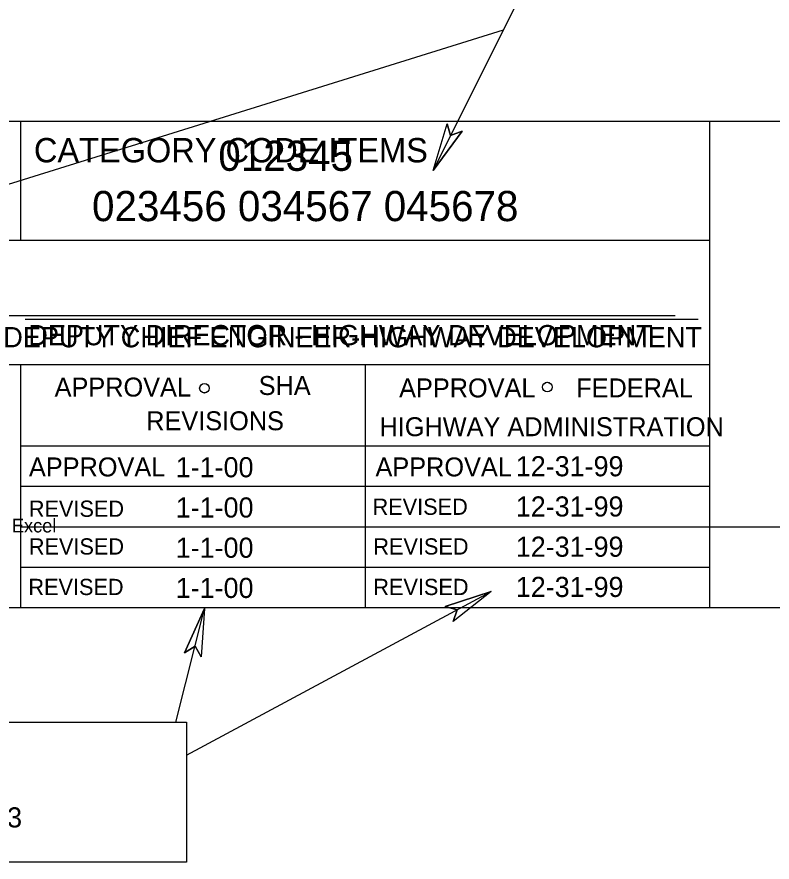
# Model space of a CAD drawing. Extents: x -0.5 to 21.6, y 4.3 to 17.8.
# Drawn here: x 1.229 to 3.481, y 5.179 to 7.7 of the extents above; entities that cross this region are included whole.
import ezdxf

# ---------------------------------------------------------------- set-up
doc = ezdxf.new("R2010")
doc.units = 0
for name, color, linetype in [('DETL-DIMS', 7, 'Continuous'), ('DETL-LINE', 7, 'Continuous'), ('DETL-NOTE', 7, 'Continuous'), ('TTLB-TEXT', 7, 'Continuous'), ('USER-BORD', 7, 'Continuous')]:
    doc.layers.add(name, color=color, linetype=linetype)

msp = doc.modelspace()

# ---------------------------------------------------------------- linework, layer by layer
at = {"layer": 'DETL-DIMS'}
for p, q in [((2.7192, 7.74), (2.4706, 7.2422)), ((2.6792, 7.6599), (1.0734, 7.16)), ((2.4706, 7.2422), (2.512, 7.3814)), ((2.5224, 7.346), (2.512, 7.3814)), ((2.4706, 7.2422), (2.557, 7.3589)), ((2.557, 7.3589), (2.5224, 7.346)), ((1.7345, 5.4977), (2.6438, 5.9866)), ((2.6438, 5.9866), (2.5059, 5.9411)), ((2.6438, 5.9866), (2.5298, 5.8967)), ((1.7034, 5.5961), (1.7884, 5.9359)), ((1.7884, 5.9359), (1.7293, 5.8033)), ((1.7884, 5.9359), (1.7782, 5.7911)), ((2.5059, 5.9411), (2.5416, 5.9317)), ((2.5416, 5.9317), (2.5298, 5.8967)), ((1.7293, 5.8033), (1.7603, 5.8234)), ((1.7603, 5.8234), (1.7782, 5.7911))]:
    msp.add_line(p, q, dxfattribs=at)
for points in [[(2.557, 7.3589), (2.4706, 7.2422), (2.512, 7.3814), (2.5224, 7.346)], [(2.5059, 5.9411), (2.6438, 5.9866), (2.5298, 5.8967), (2.5416, 5.9317)], [(1.7293, 5.8033), (1.7884, 5.9359), (1.7782, 5.7911), (1.7603, 5.8234)]]:
    msp.add_lwpolyline(points, close=True, dxfattribs=at)
at = {"layer": 'DETL-LINE'}
msp.add_lwpolyline([(0.3943, 14.1527), (0.3943, 16.2906), (7.7685, 16.2906), (7.7685, 5.9375), (0.3943, 5.9375), (0.3943, 13.6862)], dxfattribs=at)
at = {"layer": 'DETL-NOTE'}
for p, q in [((1.1851, 6.8093), (3.192, 6.8093)), ((1.2535, 6.7985), (3.2604, 6.7985))]:
    msp.add_line(p, q, dxfattribs=at)
for centre in [(1.7884, 6.5926), (2.811, 6.5959)]:
    msp.add_ellipse(centre, major_axis=(0, -0.0143), ratio=0.999903, dxfattribs=at)
at = {"layer": 'TTLB-TEXT'}
for p, q in [((7.7685, 7.3883), (0.3943, 7.3883)), ((1.2405, 7.0336), (1.2405, 7.3883)), ((3.2956, 5.9375), (3.2956, 7.3883)), ((0.3943, 7.0336), (3.2956, 7.0336)), ((0.3943, 6.6629), (1.2405, 6.6629)), ((1.2405, 6.6629), (3.2956, 6.6629)), ((1.2405, 5.9375), (1.2405, 6.6629)), ((2.2681, 6.6629), (2.2681, 5.9375)), ((1.2405, 6.4211), (3.2956, 6.4211)), ((1.2405, 6.3002), (3.2956, 6.3002)), ((1.2405, 6.1793), (3.2956, 6.1793)), ((3.2956, 6.1793), (7.7685, 6.1793)), ((1.2405, 6.0584), (3.2956, 6.0584)), ((7.7685, 5.9375), (0.3943, 5.9375))]:
    msp.add_line(p, q, dxfattribs=at)
for points in [[(0.3943, 16.2906), (7.7685, 16.2906), (7.7685, 5.9375), (0.3943, 5.9375)], [(-0.1847, 5.5961), (1.7345, 5.5961), (1.7345, 5.1791), (-0.1847, 5.1791)]]:
    msp.add_lwpolyline(points, close=True, dxfattribs=at)
for centre in [(1.7883, 6.5925), (2.811, 6.5958)]:
    msp.add_ellipse(centre, major_axis=(0, -0.0143), ratio=0.999903, dxfattribs=at)
at = {"layer": 'USER-BORD'}
for p, q in [((7.7685, 7.3883), (0.3943, 7.3883)), ((1.2405, 7.0336), (1.2405, 7.3883)), ((3.2956, 5.9375), (3.2956, 7.3883)), ((0.3943, 7.0336), (3.2956, 7.0336)), ((0.3943, 6.6629), (1.2405, 6.6629)), ((1.2405, 6.6629), (3.2956, 6.6629)), ((1.2405, 5.9375), (1.2405, 6.6629)), ((2.2681, 6.6629), (2.2681, 5.9375)), ((1.2405, 6.4211), (3.2956, 6.4211)), ((1.2405, 6.3002), (3.2956, 6.3002)), ((1.2405, 6.1793), (3.2956, 6.1793)), ((3.2956, 6.1793), (7.7685, 6.1793)), ((1.2405, 6.0584), (3.2956, 6.0584)), ((7.7685, 5.9375), (0.3943, 5.9375))]:
    msp.add_line(p, q, dxfattribs=at)

# ---------------------------------------------------------------- texts
at = {"layer": 'DETL-DIMS'}
msp.add_text('CATEGORY CODE ITEMS ', height=0.07254, dxfattribs=at).set_placement((1.2798, 7.2662))
at = {"layer": 'DETL-LINE'}
for s, height, p in [('DEPUTY DIRECTOR - HIGHWAY DEVELOPMENT', 0.0604, (1.2629, 6.7206)), ('Driven to Excel', 0.04061, (0.9815, 6.1623))]:
    msp.add_text(s, height=height, dxfattribs=at).set_placement(p)
at = {"layer": 'DETL-NOTE'}
for s, p in [('APPROVAL', (1.3415, 6.5677)), ('SHA', (1.9501, 6.5724)), ('APPROVAL', (2.369, 6.5652)), ('FEDERAL', (2.8971, 6.5653)), ('REVISIONS', (1.6146, 6.4672)), ('HIGHWAY ADMINISTRATION', (2.3105, 6.4495)), ('APPROVAL', (1.2649, 6.3295)), ('APPROVAL', (2.2985, 6.3295))]:
    msp.add_text(s, height=0.05642, dxfattribs=at).set_placement(p)
at = {"layer": 'TTLB-TEXT'}
for s, height, p in [('CATEGORY CODE ITEMS ', 0.07254, (1.2797, 7.2661)), ('            012345', 0.09, (1.4285, 7.2408)), ('023456 034567 045678', 0.09, (1.4531, 7.0908)), ('APPROVAL', 0.05642, (1.3414, 6.5676)), ('SHA', 0.05642, (1.95, 6.5723)), ('APPROVAL', 0.05642, (2.3689, 6.5651)), ('FEDERAL', 0.05642, (2.897, 6.5652)), ('REVISIONS', 0.05642, (1.6145, 6.4671)), ('HIGHWAY ADMINISTRATION', 0.05642, (2.3104, 6.4494)), ('APPROVAL', 0.05642, (1.2648, 6.3294)), ('1-1-00', 0.06, (1.7027, 6.3268)), ('APPROVAL', 0.05642, (2.2984, 6.3294)), ('12-31-99', 0.06, (2.717, 6.3298)), ('REVISED', 0.04836, (1.2645, 6.2089)), ('1-1-00', 0.06, (1.7027, 6.2068)), ('REVISED', 0.04836, (2.2897, 6.2148)), ('12-31-99', 0.06, (2.717, 6.2098)), ('REVISED', 0.04836, (1.2645, 6.0963)), ('1-1-00', 0.06, (1.7027, 6.0868)), ('REVISED', 0.04836, (2.292, 6.0963)), ('12-31-99', 0.06, (2.717, 6.0898)), ('1-1-00', 0.06, (1.7027, 5.9668)), ('12-31-99', 0.06, (2.717, 5.9698)), ('REVISED', 0.04836, (1.2632, 5.9755)), ('REVISED', 0.04836, (2.292, 5.9755)), ('LS=.06, IS=.01, WT=0, CO=0, LV=13 ', 0.06, (-0.087, 5.2824))]:
    msp.add_text(s, height=height, dxfattribs=at).set_placement(p)
at = {"layer": 'USER-BORD'}
for s, height, p in [('DEPUTY CHIEF ENGINEER-HIGHWAY DEVELOPMENT', 0.06045, (1.1883, 6.7145)), ('REVISED', 0.04836, (1.2646, 6.209)), ('REVISED', 0.04836, (2.2898, 6.2149)), ('REVISED', 0.04836, (1.2646, 6.0964)), ('REVISED', 0.04836, (2.2921, 6.0964)), ('REVISED', 0.04836, (1.2633, 5.9756)), ('REVISED', 0.04836, (2.2921, 5.9756))]:
    msp.add_text(s, height=height, dxfattribs=at).set_placement(p)

doc.saveas('drawing.dxf')
